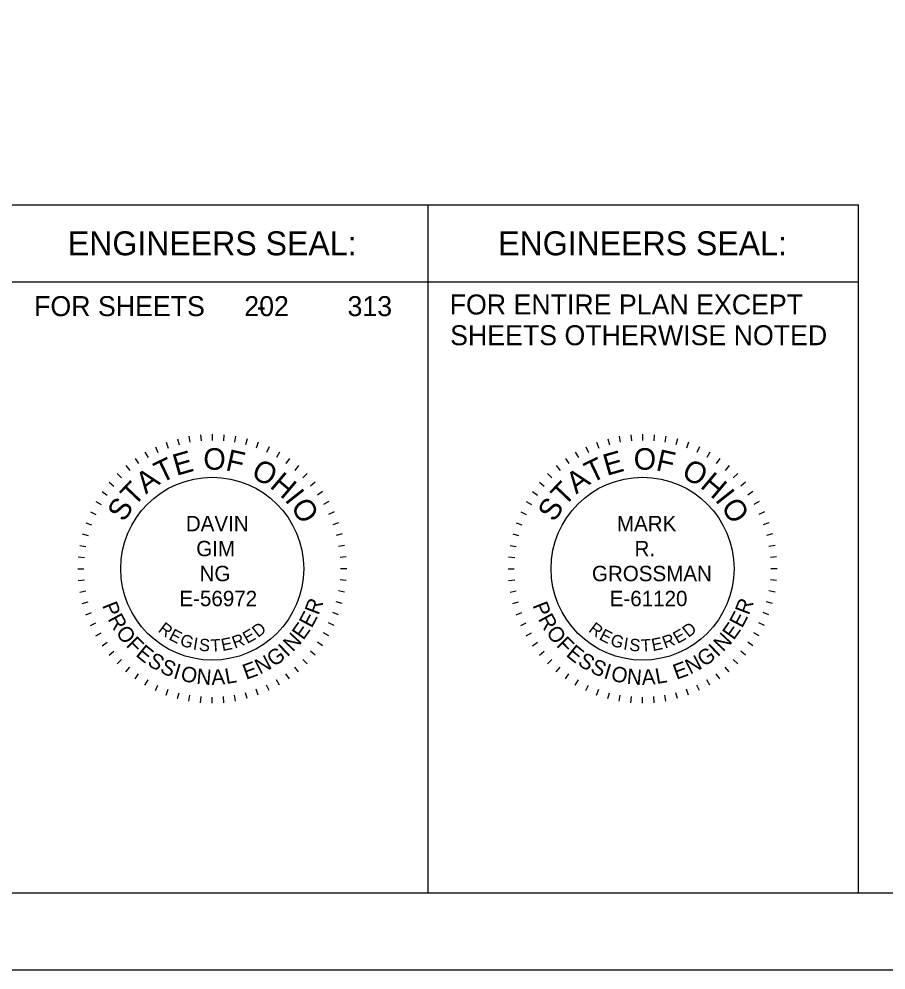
# Model space of a CAD drawing. Extents: x -42.2 to 34, y 0 to 22.
# Drawn here: x 21.71 to 27.35, y 0 to 6.19 of the extents above; entities that cross this region are included whole.
import ezdxf

# ---------------------------------------------------------------- set-up
doc = ezdxf.new("R2010")
doc.units = 0
for name, color, linetype in [('SH_Border', 7, 'Continuous'), ('SH_Cut_Line', 7, 'Continuous'), ('SH_Data', 7, 'Continuous')]:
    doc.layers.add(name, color=color, linetype=linetype)

msp = doc.modelspace()

# ---------------------------------------------------------------- linework, layer by layer
at = {"layer": 'SH_Border'}
msp.add_lwpolyline([(2, 21.5), (33.5, 21.5), (33.5, 0.5), (2, 0.5)], close=True, dxfattribs=at)
at = {"layer": 'SH_Cut_Line'}
msp.add_lwpolyline([(0, 0), (34, 0), (34, 22), (0, 22)], close=True, dxfattribs=at)
at = {"layer": 'SH_Data'}
for p, q in [((21.5739, 4.977), (24.3739, 4.977)), ((24.3739, 0.5), (24.3739, 4.977)), ((24.3739, 4.977), (27.1739, 4.977)), ((27.1739, 0.5), (27.1739, 4.977)), ((21.5739, 4.477), (24.3739, 4.477)), ((24.3739, 4.477), (27.1739, 4.477)), ((27.1739, 0.5), (27.1739, 3.75)), ((27.1739, 0.5), (27.1739, 3.75)), ((22.8172, 3.4721), (22.8242, 3.4327)), ((22.8929, 3.4821), (22.8964, 3.4422)), ((22.9692, 3.4854), (22.9692, 3.4454)), ((23.0454, 3.4821), (23.042, 3.4422)), ((23.1211, 3.4721), (23.1142, 3.4327)), ((25.6172, 3.4721), (25.6242, 3.4327)), ((25.6929, 3.4821), (25.6964, 3.4422)), ((25.7692, 3.4854), (25.7692, 3.4454)), ((25.8454, 3.4821), (25.842, 3.4422)), ((25.9211, 3.4721), (25.9142, 3.4327)), ((22.5994, 3.4034), (22.6163, 3.3672)), ((22.6699, 3.4326), (22.6836, 3.395)), ((22.7427, 3.4556), (22.7531, 3.4169)), ((23.1957, 3.4556), (23.1853, 3.4169)), ((23.2685, 3.4326), (23.2548, 3.395)), ((23.339, 3.4034), (23.3221, 3.3672)), ((25.3994, 3.4034), (25.4163, 3.3672)), ((25.4699, 3.4326), (25.4836, 3.395)), ((25.5427, 3.4556), (25.5531, 3.4169)), ((25.9957, 3.4556), (25.9853, 3.4169)), ((26.0685, 3.4326), (26.0548, 3.395)), ((26.139, 3.4034), (26.1221, 3.3672)), ((22.5317, 3.3682), (22.5517, 3.3335)), ((23.4067, 3.3682), (23.3867, 3.3335)), ((25.3317, 3.3682), (25.3517, 3.3335)), ((26.2067, 3.3682), (26.1867, 3.3335)), ((22.4067, 3.2807), (22.4325, 3.25)), ((22.4673, 3.3272), (22.4903, 3.2944)), ((23.4711, 3.3272), (23.4481, 3.2944)), ((23.5316, 3.2807), (23.5059, 3.25)), ((25.2067, 3.2807), (25.2325, 3.25)), ((25.2673, 3.3272), (25.2903, 3.2944)), ((26.2711, 3.3272), (26.2481, 3.2944)), ((26.3316, 3.2807), (26.3059, 3.25)), ((22.3505, 3.2291), (22.3788, 3.2008)), ((23.5879, 3.2291), (23.5596, 3.2008)), ((25.1505, 3.2291), (25.1788, 3.2008)), ((26.3879, 3.2291), (26.3596, 3.2008)), ((22.2989, 3.1728), (22.3295, 3.1471)), ((23.6395, 3.1728), (23.6088, 3.1471)), ((25.0989, 3.1728), (25.1295, 3.1471)), ((26.4395, 3.1728), (26.4088, 3.1471)), ((22.2524, 3.1123), (22.2852, 3.0893)), ((23.6859, 3.1123), (23.6532, 3.0893)), ((25.0524, 3.1123), (25.0852, 3.0893)), ((26.4859, 3.1123), (26.4532, 3.0893)), ((22.2114, 3.0479), (22.2461, 3.0279)), ((23.727, 3.0479), (23.6923, 3.0279)), ((25.0114, 3.0479), (25.0461, 3.0279)), ((26.527, 3.0479), (26.4923, 3.0279)), ((22.1762, 2.9802), (22.2124, 2.9633)), ((23.7622, 2.9802), (23.726, 2.9633)), ((24.9762, 2.9802), (25.0124, 2.9633)), ((26.5622, 2.9802), (26.526, 2.9633)), ((22.147, 2.9097), (22.1845, 2.896)), ((23.7914, 2.9097), (23.7538, 2.896)), ((24.947, 2.9097), (24.9845, 2.896)), ((26.5914, 2.9097), (26.5538, 2.896)), ((22.124, 2.8369), (22.1626, 2.8265)), ((23.8144, 2.8369), (23.7757, 2.8265)), ((24.924, 2.8369), (24.9626, 2.8265)), ((26.6144, 2.8369), (26.5757, 2.8265)), ((22.1075, 2.7623), (22.1469, 2.7554)), ((23.8309, 2.7623), (23.7915, 2.7554)), ((24.9075, 2.7623), (24.9469, 2.7554)), ((26.6309, 2.7623), (26.5915, 2.7554)), ((22.0975, 2.6867), (22.1374, 2.6832)), ((23.8409, 2.6867), (23.801, 2.6832)), ((24.8975, 2.6867), (24.9374, 2.6832)), ((26.6409, 2.6867), (26.601, 2.6832)), ((22.0942, 2.6104), (22.1342, 2.6104)), ((23.8442, 2.6104), (23.8042, 2.6104)), ((24.8942, 2.6104), (24.9342, 2.6104)), ((26.6442, 2.6104), (26.6042, 2.6104)), ((22.0975, 2.5341), (22.1374, 2.5376)), ((23.8409, 2.5341), (23.801, 2.5376)), ((24.8975, 2.5341), (24.9374, 2.5376)), ((26.6409, 2.5341), (26.601, 2.5376)), ((22.1075, 2.4585), (22.1469, 2.4654)), ((23.8309, 2.4585), (23.7915, 2.4654)), ((24.9075, 2.4585), (24.9469, 2.4654)), ((26.6309, 2.4585), (26.5915, 2.4654)), ((22.124, 2.3839), (22.1626, 2.3943)), ((23.8144, 2.3839), (23.7757, 2.3943)), ((24.924, 2.3839), (24.9626, 2.3943)), ((26.6144, 2.3839), (26.5757, 2.3943)), ((22.147, 2.3111), (22.1845, 2.3248)), ((23.7914, 2.3111), (23.7538, 2.3248)), ((24.947, 2.3111), (24.9845, 2.3248)), ((26.5914, 2.3111), (26.5538, 2.3248)), ((22.1762, 2.2406), (22.2124, 2.2575)), ((23.7622, 2.2406), (23.726, 2.2575)), ((24.9762, 2.2406), (25.0124, 2.2575)), ((26.5622, 2.2406), (26.526, 2.2575)), ((22.2114, 2.1729), (22.2461, 2.1929)), ((23.727, 2.1729), (23.6923, 2.1929)), ((25.0114, 2.1729), (25.0461, 2.1929)), ((26.527, 2.1729), (26.4923, 2.1929)), ((22.2524, 2.1085), (22.2852, 2.1315)), ((23.6859, 2.1085), (23.6532, 2.1315)), ((25.0524, 2.1085), (25.0852, 2.1315)), ((26.4859, 2.1085), (26.4532, 2.1315)), ((22.2989, 2.048), (22.3295, 2.0737)), ((23.6395, 2.048), (23.6088, 2.0737)), ((25.0989, 2.048), (25.1295, 2.0737)), ((26.4395, 2.048), (26.4088, 2.0737)), ((22.3505, 1.9917), (22.3788, 2.02)), ((23.5879, 1.9917), (23.5596, 2.02)), ((25.1505, 1.9917), (25.1788, 2.02)), ((26.3879, 1.9917), (26.3596, 2.02)), ((22.4067, 1.9401), (22.4325, 1.9707)), ((22.4673, 1.8936), (22.4903, 1.9264)), ((23.4711, 1.8936), (23.4481, 1.9264)), ((23.5316, 1.9401), (23.5059, 1.9707)), ((25.2067, 1.9401), (25.2325, 1.9707)), ((25.2673, 1.8936), (25.2903, 1.9264)), ((26.2711, 1.8936), (26.2481, 1.9264)), ((26.3316, 1.9401), (26.3059, 1.9707)), ((22.5317, 1.8526), (22.5517, 1.8873)), ((23.4067, 1.8526), (23.3867, 1.8873)), ((25.3317, 1.8526), (25.3517, 1.8873)), ((26.2067, 1.8526), (26.1867, 1.8873)), ((22.5994, 1.8174), (22.6163, 1.8536)), ((22.6699, 1.7882), (22.6836, 1.8258)), ((22.7427, 1.7652), (22.7531, 1.8038)), ((23.1957, 1.7652), (23.1853, 1.8038)), ((23.2685, 1.7882), (23.2548, 1.8258)), ((23.339, 1.8174), (23.3221, 1.8536)), ((25.3994, 1.8174), (25.4163, 1.8536)), ((25.4699, 1.7882), (25.4836, 1.8258)), ((25.5427, 1.7652), (25.5531, 1.8038)), ((25.9957, 1.7652), (25.9853, 1.8038)), ((26.0685, 1.7882), (26.0548, 1.8258)), ((26.139, 1.8174), (26.1221, 1.8536)), ((22.8172, 1.7487), (22.8242, 1.7881)), ((22.8929, 1.7387), (22.8964, 1.7786)), ((22.9692, 1.7354), (22.9692, 1.7754)), ((23.0454, 1.7387), (23.042, 1.7786)), ((23.1211, 1.7487), (23.1142, 1.7881)), ((25.6172, 1.7487), (25.6242, 1.7881)), ((25.6929, 1.7387), (25.6964, 1.7786)), ((25.7692, 1.7354), (25.7692, 1.7754)), ((25.8454, 1.7387), (25.842, 1.7786)), ((25.9211, 1.7487), (25.9142, 1.7881))]:
    msp.add_line(p, q, dxfattribs=at)
for centre in [(22.9692, 2.6104), (25.7692, 2.6104)]:
    msp.add_circle(centre, 0.595, dxfattribs=at)

# ---------------------------------------------------------------- texts
for s, height, p in [('ENGINEERS SEAL:', 0.156, (22.0298, 4.649)), ('ENGINEERS SEAL:', 0.156, (24.8298, 4.649)), ('FOR ENTIRE PLAN EXCEPT', 0.13, (24.5142, 4.2642)), ('FOR SHEETS       -', 0.13, (21.8104, 4.2535)), ('202', 0.13, (23.1777, 4.2535)), ('313', 0.13, (23.8495, 4.2535)), ('SHEETS OTHERWISE NOTED', 0.13, (24.5172, 4.0642)), ('DAVIN', 0.1, (22.7975, 2.8541)), ('MARK', 0.1, (25.6023, 2.8541)), ('GIM', 0.1, (22.8653, 2.6916)), ('R.', 0.1, (25.7168, 2.6916)), ('NG', 0.1, (22.8868, 2.5291)), ('GROSSMAN', 0.1, (25.4399, 2.5291)), ('E-56972', 0.1, (22.7557, 2.3666)), ('E-61120', 0.1, (25.5555, 2.3666))]:
    msp.add_text(s, height=height, dxfattribs=at).set_placement(p)
for s, height, rotation, p in [('E', 0.14, 15.75706, (22.7361, 3.2138)), ('O', 0.14, 359.78119, (22.9112, 3.2546)), ('F', 0.14, 347.43619, (23.0503, 3.2521)), ('E', 0.14, 15.75706, (25.5361, 3.2138)), ('O', 0.14, 359.78119, (25.7112, 3.2546)), ('F', 0.14, 347.43619, (25.8503, 3.2521)), ('T', 0.14, 25.71674, (22.6353, 3.1644)), ('O', 0.14, 332.25863, (23.2154, 3.2085)), ('T', 0.14, 25.71674, (25.4353, 3.1644)), ('O', 0.14, 332.25863, (26.0154, 3.2085)), ('A', 0.14, 36.47472, (22.5377, 3.0923)), ('H', 0.14, 319.91363, (23.3376, 3.142)), ('A', 0.14, 36.47472, (25.3377, 3.0923)), ('H', 0.14, 319.91363, (26.1376, 3.142)), ('T', 0.14, 46.4344, (22.4609, 3.0104)), ('T', 0.14, 46.4344, (25.2609, 3.0104)), ('I', 0.14, 308.36695, (23.4366, 3.0575)), ('I', 0.14, 308.36695, (26.2366, 3.0575)), ('S', 0.14, 57.19238, (22.3952, 2.9085)), ('O', 0.14, 303.14906, (23.4753, 3.0132)), ('S', 0.14, 57.19238, (25.1952, 2.9085)), ('O', 0.14, 303.14906, (26.2753, 3.0132)), ('R', 0.1, 69.23216, (23.6605, 2.304)), ('R', 0.1, 69.23216, (26.4605, 2.304)), ('P', 0.1, 291.49398, (22.2515, 2.3722)), ('P', 0.1, 291.49398, (25.0515, 2.3722)), ('R', 0.1, 298.73106, (22.2873, 2.2837)), ('E', 0.1, 61.99508, (23.6164, 2.2194)), ('R', 0.1, 298.73106, (25.0873, 2.2837)), ('E', 0.1, 61.99508, (26.4164, 2.2194)), ('O', 0.1, 306.46664, (22.3374, 2.1949)), ('R', 0.08, 323.2378, (22.612, 2.2045)), ('D', 0.08, 38.0378, (23.2673, 2.1592)), ('E', 0.1, 54.75801, (23.5619, 2.141)), ('O', 0.1, 306.46664, (25.1374, 2.1949)), ('R', 0.08, 323.2378, (25.412, 2.2045)), ('D', 0.08, 38.0378, (26.0673, 2.1592)), ('E', 0.1, 54.75801, (26.3619, 2.141)), ('F', 0.1, 314.7068, (22.4035, 2.1087)), ('E', 0.08, 332.42558, (22.6814, 2.1526)), ('G', 0.08, 341.00757, (22.7529, 2.1148)), ('E', 0.08, 11.68604, (23.036, 2.0738)), ('R', 0.08, 20.26803, (23.1154, 2.0898)), ('E', 0.08, 29.45581, (23.1966, 2.1198)), ('N', 0.1, 47.02243, (23.4934, 2.0654)), ('F', 0.1, 314.7068, (25.2035, 2.1087)), ('E', 0.08, 332.42558, (25.4814, 2.1526)), ('G', 0.08, 341.00757, (25.5529, 2.1148)), ('E', 0.08, 11.68604, (25.836, 2.0738)), ('R', 0.08, 20.26803, (25.9154, 2.0898)), ('E', 0.08, 29.45581, (25.9966, 2.1198)), ('N', 0.1, 47.02243, (26.2934, 2.0654)), ('E', 0.1, 321.43929, (22.4662, 2.0458)), ('I', 0.08, 350.80853, (22.8404, 2.0852)), ('S', 0.08, 355.13523, (22.8804, 2.077)), ('T', 0.08, 3.71722, (22.961, 2.0697)), ('I', 0.1, 43.28703, (23.4567, 2.0324)), ('E', 0.1, 321.43929, (25.2662, 2.0458)), ('I', 0.08, 350.80853, (25.6404, 2.0852)), ('S', 0.08, 355.13523, (25.6804, 2.077)), ('T', 0.08, 3.71722, (25.761, 2.0697)), ('I', 0.1, 43.28703, (26.2567, 2.0324)), ('S', 0.1, 328.67637, (22.5413, 1.9869)), ('N', 0.1, 27.31129, (23.2788, 1.9206)), ('G', 0.1, 35.04687, (23.3689, 1.9685)), ('S', 0.1, 328.67637, (25.3413, 1.9869)), ('N', 0.1, 27.31129, (26.0788, 1.9206)), ('G', 0.1, 35.04687, (26.1689, 1.9685)), ('S', 0.1, 335.91345, (22.6233, 1.938)), ('I', 0.1, 343.15053, (22.7108, 1.8998)), ('E', 0.1, 20.07421, (23.1895, 1.8871)), ('S', 0.1, 335.91345, (25.4233, 1.938)), ('I', 0.1, 343.15053, (25.5108, 1.8998)), ('E', 0.1, 20.07421, (25.9895, 1.8871)), ('O', 0.1, 346.88592, (22.7576, 1.8845)), ('N', 0.1, 355.12608, (22.8638, 1.8616)), ('A', 0.1, 2.86166, (22.9656, 1.8543)), ('L', 0.1, 10.09874, (23.0608, 1.8598)), ('O', 0.1, 346.88592, (25.5576, 1.8845)), ('N', 0.1, 355.12608, (25.6638, 1.8616)), ('A', 0.1, 2.86166, (25.7656, 1.8543)), ('L', 0.1, 10.09874, (25.8608, 1.8598))]:
    msp.add_text(s, height=height, rotation=rotation, dxfattribs=at).set_placement(p)

doc.saveas('drawing.dxf')
